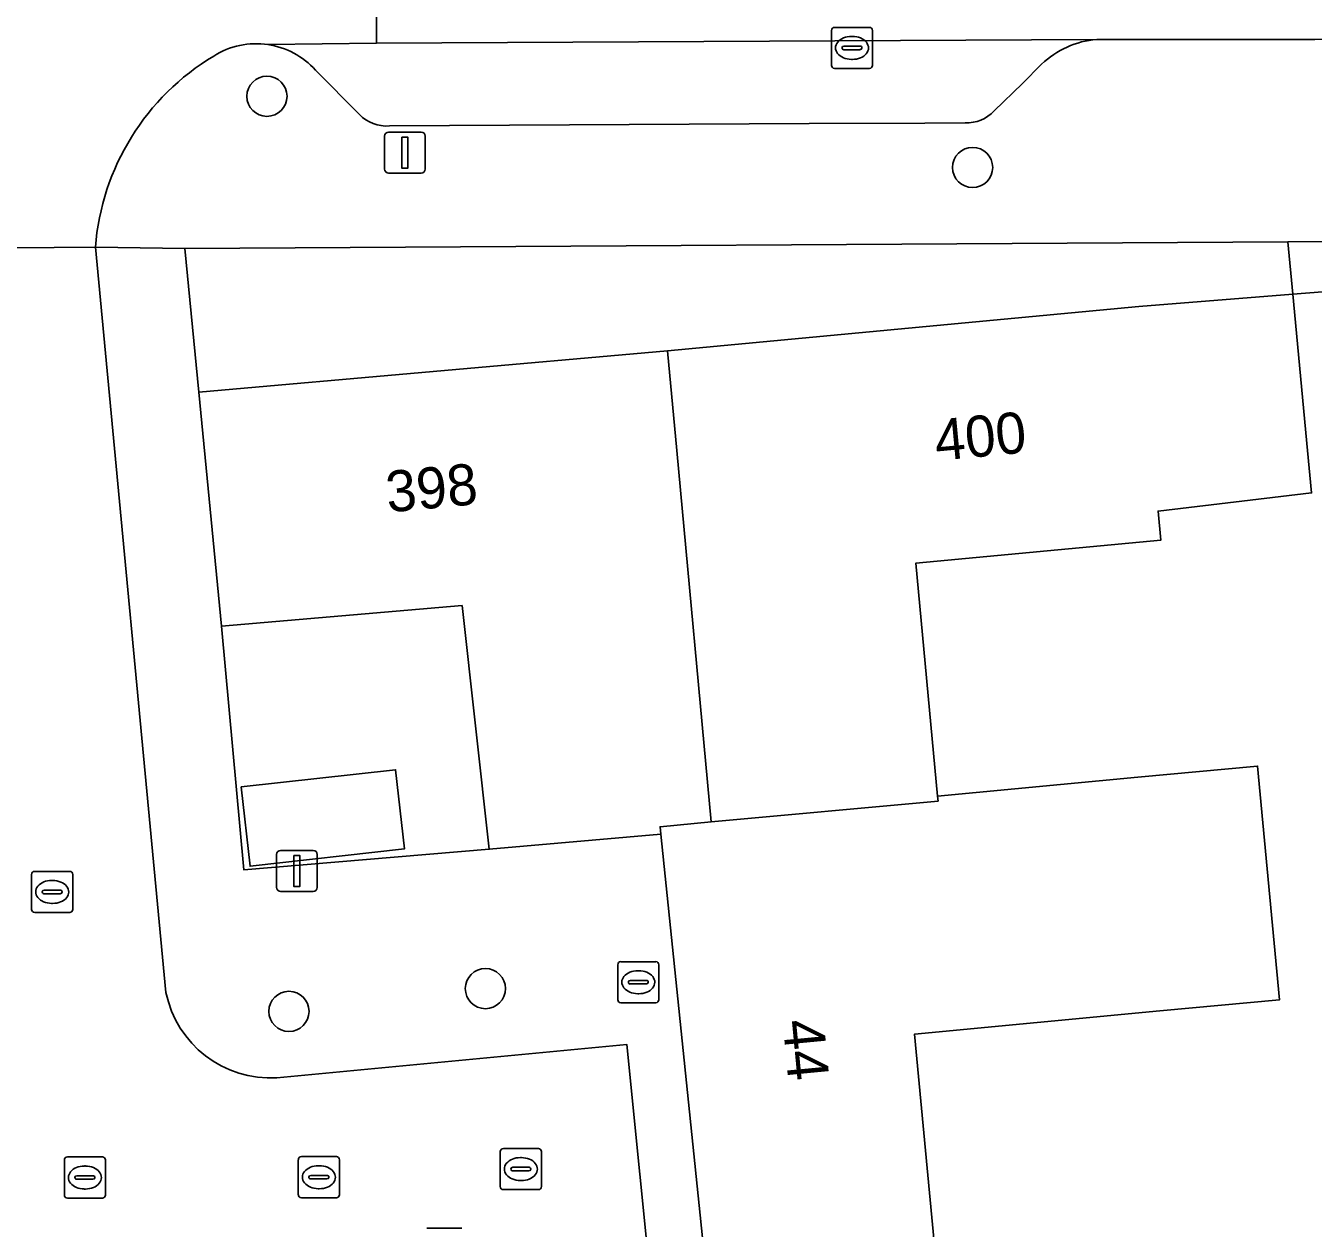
# Model space of a CAD drawing. Extents: x 157793 to 159380, y 380877 to 382313.
# Drawn here: x 158462.44 to 158493.77, y 381231.08 to 381260.34 of the extents above; entities that cross this region are included whole.
import ezdxf

# ---------------------------------------------------------------- set-up
doc = ezdxf.new("R2010")
doc.units = 0
for name, color, linetype in [('IMGEO_Boom', 7, 'Continuous'), ('IMGEO_Brandkraan', 7, 'Continuous'), ('IMGEO_Erf', 7, 'Continuous'), ('IMGEO_Groenvoorziening', 7, 'Continuous'), ('IMGEO_Kolk', 7, 'Continuous'), ('IMGEO_Lichtmast', 7, 'Continuous'), ('IMGEO_Pand', 7, 'Continuous'), ('IMGEO_Pand_nummerreeks', 7, 'Continuous'), ('IMGEO_Parkeervlak_open', 7, 'Continuous'), ('IMGEO_Rijbaan_lokaal_gesloten', 7, 'Continuous'), ('IMGEO_Rijbaan_lokaal_open', 7, 'Continuous'), ('IMGEO_Rioolput', 7, 'Continuous'), ('IMGEO_Voetpad_open', 7, 'Continuous')]:
    doc.layers.add(name, color=color, linetype=linetype)

msp = doc.modelspace()

# ---------------------------------------------------------------- linework, layer by layer
at = {"layer": 'IMGEO_Boom'}
for centre in [(158468.313, 381258.621), (158485.482, 381256.889), (158473.629, 381236.912), (158468.849, 381236.358)]:
    msp.add_circle(centre, 0.489, dxfattribs=at)
at = {"layer": 'IMGEO_Brandkraan'}
for p, q in [((158476.923, 381237.567), (158477.775, 381237.567)), ((158476.848, 381236.641), (158476.848, 381237.493)), ((158477.336, 381237.347), (158477.361, 381237.347)), ((158477.849, 381237.493), (158477.849, 381236.641)), ((158477.107, 381237.061), (158477.107, 381237.073)), ((158477.545, 381237.024), (158477.147, 381237.024)), ((158477.15, 381237.11), (158477.548, 381237.11)), ((158477.591, 381237.073), (158477.591, 381237.061)), ((158477.359, 381236.787), (158477.334, 381236.787)), ((158477.775, 381236.567), (158476.923, 381236.567))]:
    msp.add_line(p, q, dxfattribs=at)
for points in [[(158476.923, 381237.567), (158477.775, 381237.567)], [(158476.848, 381236.641), (158476.848, 381237.493)], [(158477.849, 381237.493), (158477.849, 381236.641)], [(158477.775, 381236.567), (158476.923, 381236.567)]]:
    msp.add_lwpolyline(points, dxfattribs=at)
for centre, radius, start, end in [((158476.925, 381237.491), 0.0765, 91.552, 178.448), ((158476.925, 381237.491), 0.0765, 91.552, 178.448), ((158477.773, 381237.491), 0.0765, 1.552, 88.448), ((158477.773, 381237.491), 0.0765, 1.552, 88.448), ((158477.147, 381237.07), 0.0403, 85.8775, 175.7526), ((158477.144, 381237.06), 0.0366, 178.938, 274.7102), ((158477.548, 381237.067), 0.043, 264.8664, 352.4533), ((158477.552, 381237.072), 0.0386, 1.7309, 96.639), ((158476.925, 381236.643), 0.0765, 181.552, 268.448), ((158476.925, 381236.643), 0.0765, 181.552, 268.448), ((158477.773, 381236.643), 0.0765, 271.552, 358.448), ((158477.773, 381236.643), 0.0765, 271.552, 358.448)]:
    msp.add_arc(centre, radius, start, end, dxfattribs=at)
for centre, major_axis, ratio, start_param, end_param in [((158477.335, 381237.067), (-0.387, 0.002), 0.722429, 4.712389, 7.853982), ((158477.36, 381237.067), (-0.39, 0.002), 0.717154, 1.570796, 4.712389)]:
    msp.add_ellipse(centre, major_axis=major_axis, ratio=ratio, start_param=start_param, end_param=end_param, dxfattribs=at)
at = {"layer": 'IMGEO_Erf'}
for points in [[(158489.528, 381253.507), (158493.276, 381253.804), (158493.156, 381255.076), (158466.315, 381254.92), (158466.655, 381251.426), (158478.061, 381252.429)], [(158473.06, 381246.231), (158467.205, 381245.728), (158467.748, 381239.802), (158473.723, 381240.304)], [(158467.686, 381241.817), (158471.444, 381242.237), (158471.66, 381240.309), (158467.902, 381239.889)]]:
    msp.add_lwpolyline(points, close=True, dxfattribs=at)
msp.add_lwpolyline([(158497.296, 381254.122), (158493.276, 381253.804), (158493.634, 381250), (158493.731, 381248.97), (158489.996, 381248.529), (158490.062, 381247.821), (158484.098, 381247.26), (158484.63, 381241.595), (158489.499, 381242.052), (158492.418, 381242.326), (158492.951, 381236.641), (158490.034, 381236.367), (158484.07, 381235.806), (158484.601, 381230.141), (158492.065, 381230.842), (158492.262, 381228.745), (158494.78, 381228.982)], dxfattribs=at)
at = {"layer": 'IMGEO_Groenvoorziening'}
msp.add_lwpolyline([(158505.475, 381255.148), (158493.156, 381255.076), (158493.276, 381253.804), (158497.296, 381254.122)], dxfattribs=at)
at = {"layer": 'IMGEO_Kolk'}
for p, q in [((158482.047, 381259.372), (158482.047, 381260.224)), ((158482.122, 381260.298), (158482.974, 381260.298)), ((158483.048, 381260.224), (158483.048, 381259.372)), ((158482.306, 381259.792), (158482.306, 381259.804)), ((158482.349, 381259.841), (158482.747, 381259.841)), ((158482.535, 381260.078), (158482.56, 381260.078)), ((158482.79, 381259.804), (158482.79, 381259.792)), ((158482.744, 381259.755), (158482.346, 381259.755)), ((158482.558, 381259.518), (158482.533, 381259.518)), ((158482.974, 381259.298), (158482.122, 381259.298)), ((158462.663, 381239.764), (158463.515, 381239.764)), ((158462.588, 381238.838), (158462.588, 381239.69)), ((158463.076, 381239.544), (158463.101, 381239.544)), ((158463.589, 381239.69), (158463.589, 381238.838)), ((158462.847, 381239.258), (158462.847, 381239.27)), ((158463.285, 381239.221), (158462.887, 381239.221)), ((158462.89, 381239.307), (158463.288, 381239.307)), ((158463.331, 381239.27), (158463.331, 381239.258)), ((158463.099, 381238.984), (158463.074, 381238.984)), ((158463.515, 381238.764), (158462.663, 381238.764)), ((158469.077, 381231.897), (158469.077, 381232.749)), ((158469.152, 381232.823), (158470.004, 381232.823)), ((158469.565, 381232.603), (158469.59, 381232.603)), ((158470.078, 381232.749), (158470.078, 381231.897)), ((158469.336, 381232.317), (158469.336, 381232.329)), ((158469.774, 381232.28), (158469.376, 381232.28)), ((158469.379, 381232.366), (158469.777, 381232.366)), ((158469.82, 381232.329), (158469.82, 381232.317)), ((158469.588, 381232.043), (158469.563, 381232.043)), ((158470.004, 381231.823), (158469.152, 381231.823))]:
    msp.add_line(p, q, dxfattribs=at)
for points in [[(158482.047, 381259.372), (158482.047, 381260.224)], [(158482.122, 381260.298), (158482.974, 381260.298)], [(158483.048, 381260.224), (158483.048, 381259.372)], [(158482.974, 381259.298), (158482.122, 381259.298)], [(158462.663, 381239.764), (158463.515, 381239.764)], [(158462.588, 381238.838), (158462.588, 381239.69)], [(158463.589, 381239.69), (158463.589, 381238.838)], [(158463.515, 381238.764), (158462.663, 381238.764)], [(158469.077, 381231.897), (158469.077, 381232.749)], [(158469.152, 381232.823), (158470.004, 381232.823)], [(158470.078, 381232.749), (158470.078, 381231.897)], [(158470.004, 381231.823), (158469.152, 381231.823)]]:
    msp.add_lwpolyline(points, dxfattribs=at)
for centre, radius, start, end in [((158482.124, 381260.222), 0.0765, 91.552, 178.448), ((158482.124, 381260.222), 0.0765, 91.552, 178.448), ((158482.972, 381260.222), 0.0765, 1.552, 88.448), ((158482.972, 381260.222), 0.0765, 1.552, 88.448), ((158482.346, 381259.801), 0.0403, 85.8775, 175.7526), ((158482.751, 381259.803), 0.0386, 1.7309, 96.639), ((158482.343, 381259.791), 0.0366, 178.938, 274.7102), ((158482.747, 381259.798), 0.043, 264.8664, 352.4533), ((158482.124, 381259.374), 0.0765, 181.552, 268.448), ((158482.124, 381259.374), 0.0765, 181.552, 268.448), ((158482.972, 381259.374), 0.0765, 271.552, 358.448), ((158482.972, 381259.374), 0.0765, 271.552, 358.448), ((158462.665, 381239.688), 0.0765, 91.552, 178.448), ((158462.665, 381239.688), 0.0765, 91.552, 178.448), ((158463.513, 381239.688), 0.0765, 1.552, 88.448), ((158463.513, 381239.688), 0.0765, 1.552, 88.448), ((158462.887, 381239.267), 0.0403, 85.8775, 175.7526), ((158462.884, 381239.257), 0.0366, 178.938, 274.7102), ((158463.288, 381239.264), 0.043, 264.8664, 352.4533), ((158463.292, 381239.269), 0.0386, 1.7309, 96.639), ((158462.665, 381238.84), 0.0765, 181.552, 268.448), ((158462.665, 381238.84), 0.0765, 181.552, 268.448), ((158463.513, 381238.84), 0.0765, 271.552, 358.448), ((158463.513, 381238.84), 0.0765, 271.552, 358.448), ((158469.154, 381232.747), 0.0765, 91.552, 178.448), ((158469.154, 381232.747), 0.0765, 91.552, 178.448), ((158470.002, 381232.747), 0.0765, 1.552, 88.448), ((158470.002, 381232.747), 0.0765, 1.552, 88.448), ((158469.376, 381232.326), 0.0403, 85.8775, 175.7526), ((158469.373, 381232.316), 0.0366, 178.938, 274.7102), ((158469.777, 381232.323), 0.043, 264.8664, 352.4533), ((158469.781, 381232.328), 0.0386, 1.7309, 96.639), ((158469.154, 381231.899), 0.0765, 181.552, 268.448), ((158469.154, 381231.899), 0.0765, 181.552, 268.448), ((158470.002, 381231.899), 0.0765, 271.552, 358.448), ((158470.002, 381231.899), 0.0765, 271.552, 358.448)]:
    msp.add_arc(centre, radius, start, end, dxfattribs=at)
for centre, major_axis, ratio, start_param, end_param in [((158482.534, 381259.798), (-0.387, 0.002), 0.722429, 4.712389, 7.853982), ((158482.559, 381259.798), (-0.39, 0.002), 0.717154, 1.570796, 4.712389), ((158463.075, 381239.264), (-0.387, 0.002), 0.722429, 4.712389, 7.853982), ((158463.1, 381239.264), (-0.39, 0.002), 0.717154, 1.570796, 4.712389), ((158469.564, 381232.323), (-0.387, 0.002), 0.722429, 4.712389, 7.853982), ((158469.589, 381232.323), (-0.39, 0.002), 0.717154, 1.570796, 4.712389)]:
    msp.add_ellipse(centre, major_axis=major_axis, ratio=ratio, start_param=start_param, end_param=end_param, dxfattribs=at)
at = {"layer": 'IMGEO_Lichtmast'}
for p, q in [((158471.174, 381256.851), (158471.174, 381257.651)), ((158471.174, 381257.651), (158471.174, 381256.851)), ((158471.274, 381257.751), (158472.064, 381257.751)), ((158472.064, 381257.751), (158471.274, 381257.751)), ((158472.164, 381257.651), (158472.164, 381256.851)), ((158472.164, 381256.851), (158472.164, 381257.651)), ((158472.064, 381256.751), (158471.274, 381256.751)), ((158471.274, 381256.751), (158472.064, 381256.751)), ((158468.547, 381239.374), (158468.547, 381240.174)), ((158468.547, 381240.174), (158468.547, 381239.374)), ((158468.647, 381240.274), (158469.437, 381240.274)), ((158469.437, 381240.274), (158468.647, 381240.274)), ((158469.537, 381240.174), (158469.537, 381239.374)), ((158469.537, 381239.374), (158469.537, 381240.174)), ((158469.437, 381239.274), (158468.647, 381239.274)), ((158468.647, 381239.274), (158469.437, 381239.274))]:
    msp.add_line(p, q, dxfattribs=at)
for points in [[(158471.594, 381257.626), (158471.744, 381257.626), (158471.744, 381256.876), (158471.594, 381256.876), (158471.594, 381257.626)], [(158468.967, 381240.149), (158469.117, 381240.149), (158469.117, 381239.399), (158468.967, 381239.399), (158468.967, 381240.149)]]:
    msp.add_lwpolyline(points, dxfattribs=at)
for centre, start, end in [((158471.274, 381257.651), 90, 180), ((158471.274, 381257.651), 90, 180), ((158472.064, 381257.651), 0, 90), ((158472.064, 381257.651), 360, 90), ((158471.274, 381256.851), 180, 270), ((158471.274, 381256.851), 180, 270), ((158472.064, 381256.851), 270, 0), ((158472.064, 381256.851), 270, 0), ((158468.647, 381240.174), 90, 180), ((158468.647, 381240.174), 90, 180), ((158469.437, 381240.174), 0, 90), ((158469.437, 381240.174), 360, 90), ((158468.647, 381239.374), 180, 270), ((158468.647, 381239.374), 180, 270), ((158469.437, 381239.374), 270, 0), ((158469.437, 381239.374), 270, 0)]:
    msp.add_arc(centre, 0.1, start, end, dxfattribs=at)
at = {"layer": 'IMGEO_Pand'}
for points in [[(158479.12, 381240.97), (158484.641, 381241.474), (158484.63, 381241.595), (158484.098, 381247.26), (158490.062, 381247.821), (158489.996, 381248.529), (158493.731, 381248.97), (158493.634, 381250), (158493.276, 381253.804), (158489.528, 381253.507), (158478.061, 381252.429), (158478.285, 381250)], [(158478.061, 381252.429), (158466.655, 381251.426), (158467.205, 381245.728), (158473.06, 381246.231), (158473.723, 381240.304), (158477.894, 381240.668), (158477.877, 381240.851), (158479.12, 381240.97), (158478.285, 381250)], [(158484.63, 381241.595), (158484.641, 381241.474), (158479.12, 381240.97), (158477.877, 381240.851), (158477.894, 381240.668), (158479.065, 381229.354), (158480.471, 381229.444), (158484.615, 381229.99), (158484.601, 381230.141), (158484.07, 381235.806), (158490.034, 381236.367), (158492.951, 381236.641), (158492.418, 381242.326), (158489.499, 381242.052)], [(158467.686, 381241.817), (158467.902, 381239.889), (158471.66, 381240.309), (158471.444, 381242.237)]]:
    msp.add_lwpolyline(points, close=True, dxfattribs=at)
at = {"layer": 'IMGEO_Parkeervlak_open'}
for points in [[(158470.976, 381259.911), (158468.336, 381259.878)], [(158488.504, 381260.004), (158470.976, 381259.911)], [(158469.494, 381259.259), (158470.564, 381258.177)], [(158486.694, 381258.928), (158487.162, 381259.403)], [(158486.005, 381258.263), (158486.694, 381258.928)], [(158471.292, 381257.899), (158481.508, 381257.956)], [(158481.508, 381257.956), (158484.319, 381257.971)], [(158484.319, 381257.971), (158485.302, 381257.975)]]:
    msp.add_lwpolyline(points, dxfattribs=at)
for centre, radius, start, end in [((158468.051, 381257.953), 1.946, 42.1573, 81.5899), ((158488.673, 381257.828), 2.182, 94.4362, 133.8132), ((158485.344, 381258.874), 0.9, 267.304, 317.2512), ((158471.23, 381258.828), 0.931, 224.3639, 273.8356)]:
    msp.add_arc(centre, radius, start, end, dxfattribs=at)
at = {"layer": 'IMGEO_Rijbaan_lokaal_gesloten'}
msp.add_lwpolyline([(158522.462, 381266.113), (158520.389, 381266.13), (158503.707, 381266.022), (158502.167, 381266.021), (158489.605, 381265.971), (158488.49, 381265.978), (158471.946, 381265.897), (158470.948, 381265.889), (158470.976, 381259.911), (158488.504, 381260.004), (158493.599, 381260), (158493.81, 381260.001), (158506.971, 381260.049), (158508.067, 381260.053), (158510.744, 381260.078), (158522.472, 381260.13)], close=True, dxfattribs=at)
at = {"layer": 'IMGEO_Rijbaan_lokaal_open'}
for points in [[(158468.336, 381259.878), (158470.976, 381259.911), (158470.948, 381265.889)], [(158464.139, 381254.952), (158459.094, 381254.91), (158460.643, 381238.555), (158461.11, 381233.537), (158453.64, 381232.867), (158451.137, 381232.661), (158451.618, 381227.629), (158467.244, 381229.063)], [(158459.094, 381254.91), (158464.139, 381254.952)], [(158465.857, 381236.82), (158464.139, 381254.952)], [(158479.886, 381207.486), (158477.07, 381235.549), (158468.557, 381234.743)]]:
    msp.add_lwpolyline(points, dxfattribs=at)
for centre, radius, start, end in [((158468.053, 381257.958), 1.941, 81.6033, 122.2178), ((158470.096, 381254.478), 5.976, 121.0011, 175.4502), ((158468.399, 381237.331), 2.593, 191.3691, 273.4917)]:
    msp.add_arc(centre, radius, start, end, dxfattribs=at)
at = {"layer": 'IMGEO_Rioolput'}
for p, q in [((158473.991, 381232.095), (158473.991, 381232.947)), ((158474.066, 381233.021), (158474.918, 381233.021)), ((158474.992, 381232.947), (158474.992, 381232.095)), ((158463.384, 381231.89), (158463.384, 381232.742)), ((158463.459, 381232.816), (158464.311, 381232.816)), ((158463.872, 381232.596), (158463.897, 381232.596)), ((158464.385, 381232.742), (158464.385, 381231.89)), ((158474.293, 381232.564), (158474.691, 381232.564)), ((158474.479, 381232.801), (158474.504, 381232.801)), ((158463.643, 381232.31), (158463.643, 381232.322)), ((158464.081, 381232.273), (158463.683, 381232.273)), ((158463.686, 381232.359), (158464.084, 381232.359)), ((158464.127, 381232.322), (158464.127, 381232.31)), ((158474.25, 381232.515), (158474.25, 381232.527)), ((158474.688, 381232.478), (158474.29, 381232.478)), ((158474.502, 381232.241), (158474.477, 381232.241)), ((158474.734, 381232.527), (158474.734, 381232.515)), ((158463.895, 381232.036), (158463.87, 381232.036)), ((158474.918, 381232.021), (158474.066, 381232.021)), ((158464.311, 381231.816), (158463.459, 381231.816)), ((158472.206, 381231.081), (158473.058, 381231.081))]:
    msp.add_line(p, q, dxfattribs=at)
for points in [[(158473.991, 381232.095), (158473.991, 381232.947)], [(158474.066, 381233.021), (158474.918, 381233.021)], [(158474.992, 381232.947), (158474.992, 381232.095)], [(158463.384, 381231.89), (158463.384, 381232.742)], [(158463.459, 381232.816), (158464.311, 381232.816)], [(158464.385, 381232.742), (158464.385, 381231.89)], [(158474.918, 381232.021), (158474.066, 381232.021)], [(158464.311, 381231.816), (158463.459, 381231.816)], [(158472.206, 381231.081), (158473.058, 381231.081)]]:
    msp.add_lwpolyline(points, dxfattribs=at)
for centre, radius, start, end in [((158474.068, 381232.945), 0.0765, 91.552, 178.448), ((158474.068, 381232.945), 0.0765, 91.552, 178.448), ((158474.916, 381232.945), 0.0765, 1.552, 88.448), ((158474.916, 381232.945), 0.0765, 1.552, 88.448), ((158463.461, 381232.74), 0.0765, 91.552, 178.448), ((158463.461, 381232.74), 0.0765, 91.552, 178.448), ((158464.309, 381232.74), 0.0765, 1.552, 88.448), ((158464.309, 381232.74), 0.0765, 1.552, 88.448), ((158474.29, 381232.524), 0.0403, 85.8775, 175.7526), ((158474.695, 381232.526), 0.0386, 1.7309, 96.639), ((158463.683, 381232.319), 0.0403, 85.8775, 175.7526), ((158463.68, 381232.309), 0.0366, 178.938, 274.7102), ((158464.084, 381232.316), 0.043, 264.8664, 352.4533), ((158464.088, 381232.321), 0.0386, 1.7309, 96.639), ((158474.287, 381232.514), 0.0366, 178.938, 274.7102), ((158474.691, 381232.521), 0.043, 264.8664, 352.4533), ((158474.068, 381232.097), 0.0765, 181.552, 268.448), ((158474.068, 381232.097), 0.0765, 181.552, 268.448), ((158474.916, 381232.097), 0.0765, 271.552, 358.448), ((158474.916, 381232.097), 0.0765, 271.552, 358.448), ((158463.461, 381231.892), 0.0765, 181.552, 268.448), ((158463.461, 381231.892), 0.0765, 181.552, 268.448), ((158464.309, 381231.892), 0.0765, 271.552, 358.448), ((158464.309, 381231.892), 0.0765, 271.552, 358.448)]:
    msp.add_arc(centre, radius, start, end, dxfattribs=at)
for centre, major_axis, ratio, start_param, end_param in [((158463.871, 381232.316), (-0.387, 0.002), 0.722429, 4.712389, 7.853982), ((158463.896, 381232.316), (-0.39, 0.002), 0.717154, 1.570796, 4.712389), ((158474.478, 381232.521), (-0.387, 0.002), 0.722429, 4.712389, 7.853982), ((158474.503, 381232.521), (-0.39, 0.002), 0.717154, 1.570796, 4.712389)]:
    msp.add_ellipse(centre, major_axis=major_axis, ratio=ratio, start_param=start_param, end_param=end_param, dxfattribs=at)
at = {"layer": 'IMGEO_Voetpad_open'}
for points in [[(158493.81, 381260.001), (158493.599, 381260), (158488.504, 381260.004)], [(158470.564, 381258.177), (158469.494, 381259.259)], [(158487.162, 381259.403), (158486.694, 381258.928), (158486.005, 381258.263)], [(158485.302, 381257.975), (158484.319, 381257.971), (158481.508, 381257.956), (158471.292, 381257.899)], [(158464.139, 381254.952), (158466.315, 381254.92), (158493.156, 381255.076), (158505.475, 381255.148), (158506.263, 381256.131), (158508.826, 381256.141), (158513.546, 381256.159), (158517.527, 381256.175), (158521.313, 381256.189), (158521.769, 381252.96), (158525.854, 381253.515), (158529.939, 381253.992)], [(158477.894, 381240.668), (158473.723, 381240.304), (158467.748, 381239.802), (158467.205, 381245.728), (158466.655, 381251.426), (158466.315, 381254.92), (158464.139, 381254.952), (158465.857, 381236.82)], [(158481.475, 381201.277), (158481.008, 381206.267), (158481.261, 381206.29), (158481.223, 381206.705), (158479.065, 381229.354), (158477.894, 381240.668)], [(158468.557, 381234.743), (158477.07, 381235.549), (158479.886, 381207.486)]]:
    msp.add_lwpolyline(points, dxfattribs=at)
for centre, radius, start, end in [((158468.053, 381257.958), 1.941, 81.6033, 122.2178), ((158468.051, 381257.953), 1.946, 42.1573, 81.5899), ((158488.673, 381257.828), 2.182, 94.4362, 133.8132), ((158470.096, 381254.478), 5.976, 121.0011, 175.4502), ((158485.344, 381258.874), 0.9, 267.304, 317.2512), ((158471.23, 381258.828), 0.931, 224.3639, 273.8356), ((158468.399, 381237.331), 2.593, 191.3691, 273.4917)]:
    msp.add_arc(centre, radius, start, end, dxfattribs=at)

# ---------------------------------------------------------------- texts
at = {"layer": 'IMGEO_Pand_nummerreeks'}
for s, rotation, p in [('400', 5.371, (158484.604, 381249.751)), ('398', 5.3697, (158471.253, 381248.495)), ('44', 275.449, (158480.859, 381236.122))]:
    msp.add_text(s, height=1, rotation=rotation, dxfattribs=at).set_placement(p)

doc.saveas('drawing.dxf')
